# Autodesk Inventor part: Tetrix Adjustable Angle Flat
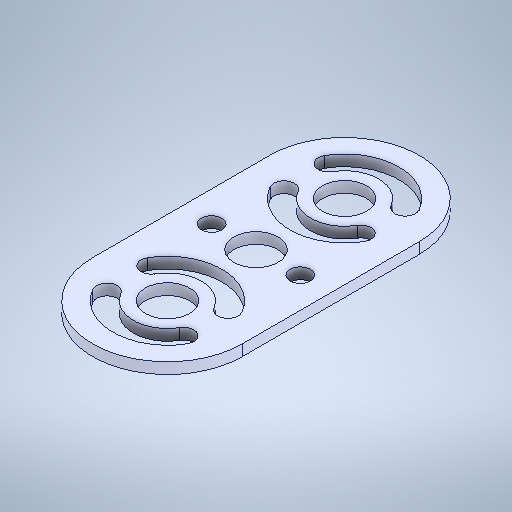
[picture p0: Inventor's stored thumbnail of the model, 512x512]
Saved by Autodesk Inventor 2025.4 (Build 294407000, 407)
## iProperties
Created: 2021-10
Part Number: Tetrix Adjustable Angle Flat
Material: Genérico
Document SubType Name: Modeling
Designer: usuario
Density: 1 g/cm^3
Appearance: Valor por defecto
Author: usuario
Sending System: SolidWorks 2016
Last Author: LENOVO
Last Saved: 2021-10-26
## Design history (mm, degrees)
feature "Boss-Extrude1"
node "Plane1"
node "Sólido1"
